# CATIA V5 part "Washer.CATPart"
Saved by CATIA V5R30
Part number: Washer
Bounding box of the stored display mesh (mm): x -7.786 to 7.786, y 0 to 1.092, z -7.938 to 7.938
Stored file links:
  D:\OneDrive\OneDrive - Carleton University\Courses\aero2001\Labs\CAD\Homework\Week 4\Components\Q5\Washer.CATPart
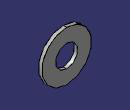
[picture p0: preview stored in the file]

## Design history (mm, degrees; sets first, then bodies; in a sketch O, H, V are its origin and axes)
Set1
  DatumSurface1 to DatumSurface6
Body1 (main body)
